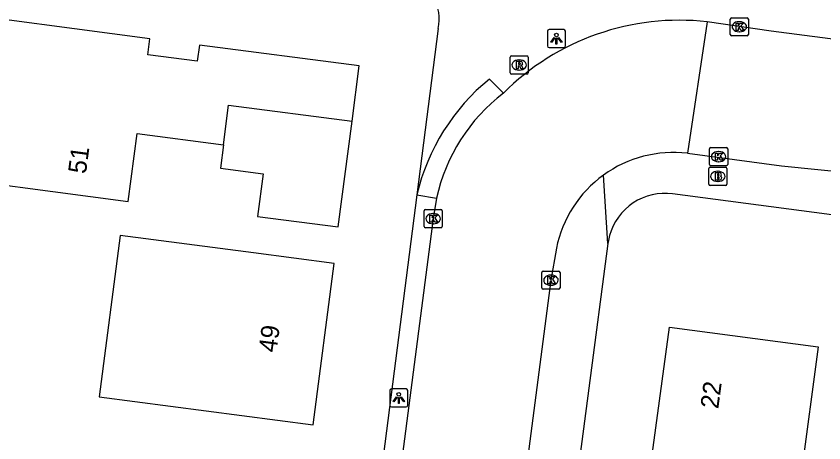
# Model space of a CAD drawing. Extents: x 162186 to 163152, y 385513 to 386513.
# Drawn here: x 162356.56 to 162401.21, y 386304.37 to 386327.96 of the extents above; entities that cross this region are included whole.
import ezdxf

# ---------------------------------------------------------------- set-up
doc = ezdxf.new("R2010")
doc.units = 0
for name, color, linetype in [('IMGEO_Brandkraan', 7, 'Continuous'), ('IMGEO_Kolk', 7, 'Continuous'), ('IMGEO_Lichtpunt', 7, 'Continuous'), ('IMGEO_Pand', 7, 'Continuous'), ('IMGEO_Pand_nummerreeks', 7, 'Continuous'), ('IMGEO_Rijbaan_lokaal_open', 7, 'Continuous'), ('IMGEO_Rioolput', 7, 'Continuous'), ('IMGEO_Voetpad_open', 7, 'Continuous')]:
    doc.layers.add(name, color=color, linetype=linetype)

msp = doc.modelspace()

# ---------------------------------------------------------------- linework, layer by layer
at = {"layer": 'IMGEO_Brandkraan'}
for p, q in [((162394.851, 386318.679), (162394.851, 386319.531)), ((162394.926, 386319.605), (162395.778, 386319.605)), ((162395.852, 386319.531), (162395.852, 386318.679)), ((162395.339, 386319.385), (162395.364, 386319.385)), ((162395.778, 386318.605), (162394.926, 386318.605)), ((162395.362, 386318.825), (162395.337, 386318.825))]:
    msp.add_line(p, q, dxfattribs=at)
for points in [[(162394.851, 386318.679), (162394.851, 386319.531)], [(162394.926, 386319.605), (162395.778, 386319.605)], [(162395.852, 386319.531), (162395.852, 386318.679)], [(162395.199, 386319.305), (162395.199, 386318.905), (162395.412, 386318.905)], [(162395.43, 386319.305), (162395.199, 386319.305)], [(162395.378, 386319.224), (162395.324, 386319.224), (162395.324, 386319.148)], [(162395.324, 386319.148), (162395.377, 386319.148)], [(162395.386, 386319.072), (162395.324, 386319.072), (162395.324, 386318.991)], [(162395.324, 386318.991), (162395.386, 386318.991)], [(162395.778, 386318.605), (162394.926, 386318.605)]]:
    msp.add_lwpolyline(points, dxfattribs=at)
for centre, radius, start, end in [((162394.928, 386319.529), 0.0765, 91.552, 178.448), ((162394.928, 386319.529), 0.0765, 91.552, 178.448), ((162395.776, 386319.529), 0.0765, 1.552, 88.448), ((162395.776, 386319.529), 0.0765, 1.552, 88.448), ((162395.379, 386319.186), 0.0379, 267.8285, 90.9355), ((162395.387, 386319.031), 0.0404, 269.8759, 90.5077), ((162395.434, 386319.16), 0.145, 59.4692, 91.5367), ((162395.459, 386319.207), 0.0922, 285.5137, 58.1501), ((162395.464, 386319.015), 0.105, 301.3115, 78.989), ((162394.928, 386318.681), 0.0765, 181.552, 268.448), ((162394.928, 386318.681), 0.0765, 181.552, 268.448), ((162395.418, 386319.156), 0.251, 268.6676, 293.5347), ((162395.776, 386318.681), 0.0765, 271.552, 358.448), ((162395.776, 386318.681), 0.0765, 271.552, 358.448)]:
    msp.add_arc(centre, radius, start, end, dxfattribs=at)
for centre, major_axis, ratio, start_param, end_param in [((162395.338, 386319.105), (-0.387, 0.002), 0.722429, 4.712389, 7.853982), ((162395.363, 386319.105), (-0.39, 0.002), 0.717154, 1.570796, 4.712389)]:
    msp.add_ellipse(centre, major_axis=major_axis, ratio=ratio, start_param=start_param, end_param=end_param, dxfattribs=at)
at = {"layer": 'IMGEO_Kolk'}
for p, q in [((162396.037, 386326.951), (162396.037, 386327.803)), ((162396.112, 386327.877), (162396.964, 386327.877)), ((162396.525, 386327.657), (162396.55, 386327.657)), ((162397.038, 386327.803), (162397.038, 386326.951)), ((162396.548, 386327.097), (162396.523, 386327.097)), ((162396.964, 386326.877), (162396.112, 386326.877)), ((162394.892, 386319.77), (162394.892, 386320.622)), ((162394.967, 386320.696), (162395.819, 386320.696)), ((162395.38, 386320.476), (162395.405, 386320.476)), ((162395.893, 386320.622), (162395.893, 386319.77)), ((162395.403, 386319.916), (162395.378, 386319.916)), ((162395.819, 386319.696), (162394.967, 386319.696)), ((162379.111, 386316.342), (162379.111, 386317.194)), ((162379.186, 386317.268), (162380.038, 386317.268)), ((162380.112, 386317.194), (162380.112, 386316.342)), ((162379.599, 386317.048), (162379.624, 386317.048)), ((162379.622, 386316.488), (162379.597, 386316.488)), ((162380.038, 386316.268), (162379.186, 386316.268)), ((162385.624, 386312.94), (162385.624, 386313.792)), ((162385.699, 386313.866), (162386.551, 386313.866)), ((162386.112, 386313.646), (162386.137, 386313.646)), ((162386.625, 386313.792), (162386.625, 386312.94)), ((162386.551, 386312.866), (162385.699, 386312.866)), ((162386.135, 386313.086), (162386.11, 386313.086))]:
    msp.add_line(p, q, dxfattribs=at)
for points in [[(162396.037, 386326.951), (162396.037, 386327.803)], [(162396.112, 386327.877), (162396.964, 386327.877)], [(162396.358, 386327.577), (162396.481, 386327.577), (162396.481, 386327.426), (162396.611, 386327.577), (162396.775, 386327.577), (162396.629, 386327.426), (162396.782, 386327.177), (162396.63, 386327.177), (162396.545, 386327.341), (162396.481, 386327.274), (162396.481, 386327.177), (162396.358, 386327.177), (162396.358, 386327.577)], [(162397.038, 386327.803), (162397.038, 386326.951)], [(162396.964, 386326.877), (162396.112, 386326.877)], [(162394.892, 386319.77), (162394.892, 386320.622)], [(162394.967, 386320.696), (162395.819, 386320.696)], [(162395.213, 386320.396), (162395.336, 386320.396), (162395.336, 386320.245), (162395.466, 386320.396), (162395.63, 386320.396), (162395.484, 386320.245), (162395.637, 386319.996), (162395.485, 386319.996), (162395.4, 386320.16), (162395.336, 386320.093), (162395.336, 386319.996), (162395.213, 386319.996), (162395.213, 386320.396)], [(162395.893, 386320.622), (162395.893, 386319.77)], [(162395.819, 386319.696), (162394.967, 386319.696)], [(162379.111, 386316.342), (162379.111, 386317.194)], [(162379.186, 386317.268), (162380.038, 386317.268)], [(162380.112, 386317.194), (162380.112, 386316.342)], [(162379.432, 386316.968), (162379.555, 386316.968), (162379.555, 386316.817), (162379.685, 386316.968), (162379.849, 386316.968), (162379.703, 386316.817), (162379.856, 386316.568), (162379.704, 386316.568), (162379.619, 386316.732), (162379.555, 386316.665), (162379.555, 386316.568), (162379.432, 386316.568), (162379.432, 386316.968)], [(162380.038, 386316.268), (162379.186, 386316.268)], [(162385.624, 386312.94), (162385.624, 386313.792)], [(162385.699, 386313.866), (162386.551, 386313.866)], [(162386.625, 386313.792), (162386.625, 386312.94)], [(162385.945, 386313.566), (162386.068, 386313.566), (162386.068, 386313.415), (162386.198, 386313.566), (162386.362, 386313.566), (162386.216, 386313.415), (162386.369, 386313.166), (162386.217, 386313.166), (162386.132, 386313.33), (162386.068, 386313.263), (162386.068, 386313.166), (162385.945, 386313.166), (162385.945, 386313.566)], [(162386.551, 386312.866), (162385.699, 386312.866)]]:
    msp.add_lwpolyline(points, dxfattribs=at)
for centre, start, end in [((162396.114, 386327.801), 91.552, 178.448), ((162396.114, 386327.801), 91.552, 178.448), ((162396.962, 386327.801), 1.552, 88.448), ((162396.962, 386327.801), 1.552, 88.448), ((162396.114, 386326.953), 181.552, 268.448), ((162396.114, 386326.953), 181.552, 268.448), ((162396.962, 386326.953), 271.552, 358.448), ((162396.962, 386326.953), 271.552, 358.448), ((162394.969, 386320.62), 91.552, 178.448), ((162394.969, 386320.62), 91.552, 178.448), ((162395.817, 386320.62), 1.552, 88.448), ((162395.817, 386320.62), 1.552, 88.448), ((162394.969, 386319.772), 181.552, 268.448), ((162394.969, 386319.772), 181.552, 268.448), ((162395.817, 386319.772), 271.552, 358.448), ((162395.817, 386319.772), 271.552, 358.448), ((162379.188, 386317.192), 91.552, 178.448), ((162379.188, 386317.192), 91.552, 178.448), ((162380.036, 386317.192), 1.552, 88.448), ((162380.036, 386317.192), 1.552, 88.448), ((162379.188, 386316.344), 181.552, 268.448), ((162379.188, 386316.344), 181.552, 268.448), ((162380.036, 386316.344), 271.552, 358.448), ((162380.036, 386316.344), 271.552, 358.448), ((162385.701, 386313.79), 91.552, 178.448), ((162385.701, 386313.79), 91.552, 178.448), ((162386.549, 386313.79), 1.552, 88.448), ((162386.549, 386313.79), 1.552, 88.448), ((162385.701, 386312.942), 181.552, 268.448), ((162385.701, 386312.942), 181.552, 268.448), ((162386.549, 386312.942), 271.552, 358.448), ((162386.549, 386312.942), 271.552, 358.448)]:
    msp.add_arc(centre, 0.0765, start, end, dxfattribs=at)
for centre, major_axis, ratio, start_param, end_param in [((162396.524, 386327.377), (-0.387, 0.002), 0.722429, 4.712389, 7.853982), ((162396.549, 386327.377), (-0.39, 0.002), 0.717154, 1.570796, 4.712389), ((162395.379, 386320.196), (-0.387, 0.002), 0.722429, 4.712389, 7.853982), ((162395.404, 386320.196), (-0.39, 0.002), 0.717154, 1.570796, 4.712389), ((162379.598, 386316.768), (-0.387, 0.002), 0.722429, 4.712389, 7.853982), ((162379.623, 386316.768), (-0.39, 0.002), 0.717154, 1.570796, 4.712389), ((162386.111, 386313.366), (-0.387, 0.002), 0.722429, 4.712389, 7.853982), ((162386.136, 386313.366), (-0.39, 0.002), 0.717154, 1.570796, 4.712389)]:
    msp.add_ellipse(centre, major_axis=major_axis, ratio=ratio, start_param=start_param, end_param=end_param, dxfattribs=at)
at = {"layer": 'IMGEO_Lichtpunt'}
for p, q in [((162385.926, 386327.124), (162385.926, 386326.317)), ((162385.926, 386327.124), (162385.926, 386326.317)), ((162386.828, 386327.219), (162386.02, 386327.219)), ((162386.828, 386327.219), (162386.02, 386327.219)), ((162386.922, 386326.317), (162386.922, 386327.124)), ((162386.922, 386326.317), (162386.922, 386327.124)), ((162386.02, 386326.223), (162386.828, 386326.223)), ((162386.02, 386326.223), (162386.828, 386326.223)), ((162377.212, 386307.261), (162377.212, 386306.454)), ((162377.212, 386307.261), (162377.212, 386306.454)), ((162378.114, 386307.356), (162377.306, 386307.356)), ((162378.114, 386307.356), (162377.306, 386307.356)), ((162378.208, 386306.454), (162378.208, 386307.261)), ((162378.208, 386306.454), (162378.208, 386307.261)), ((162377.306, 386306.36), (162378.114, 386306.36)), ((162377.306, 386306.36), (162378.114, 386306.36))]:
    msp.add_line(p, q, dxfattribs=at)
for points in [[(162386.3, 386326.788), (162386.339, 386326.76), (162386.151, 386326.498), (162386.113, 386326.525), (162386.3, 386326.788)], [(162386.402, 386326.74), (162386.449, 386326.74), (162386.449, 386326.418), (162386.402, 386326.418), (162386.402, 386326.74)], [(162386.512, 386326.76), (162386.55, 386326.787), (162386.737, 386326.525), (162386.698, 386326.497), (162386.512, 386326.76)], [(162377.586, 386306.925), (162377.625, 386306.897), (162377.437, 386306.635), (162377.399, 386306.662), (162377.586, 386306.925)], [(162377.798, 386306.897), (162377.836, 386306.924), (162378.023, 386306.662), (162377.984, 386306.634), (162377.798, 386306.897)], [(162377.688, 386306.877), (162377.735, 386306.877), (162377.735, 386306.555), (162377.688, 386306.555), (162377.688, 386306.877)]]:
    msp.add_lwpolyline(points, dxfattribs=at)
for centre in [(162386.425, 386326.922), (162377.711, 386307.059)]:
    msp.add_circle(centre, 0.0994, dxfattribs=at)
for centre, start, end in [((162386.02, 386327.124), 90, 180), ((162386.02, 386327.124), 90, 180), ((162386.828, 386327.124), 0, 90), ((162386.828, 386327.124), 0, 90), ((162386.02, 386326.317), 180, 270), ((162386.02, 386326.317), 180, 270), ((162386.828, 386326.317), 270, 0), ((162386.828, 386326.317), 270, 360), ((162377.306, 386307.261), 90, 180), ((162377.306, 386307.261), 90, 180), ((162378.114, 386307.261), 0, 90), ((162378.114, 386307.261), 0, 90), ((162377.306, 386306.454), 180, 270), ((162377.306, 386306.454), 180, 270), ((162378.114, 386306.454), 270, 0), ((162378.114, 386306.454), 270, 360)]:
    msp.add_arc(centre, 0.0946, start, end, dxfattribs=at)
at = {"layer": 'IMGEO_Pand'}
for points in [[(162375.128, 386322.164), (162375.526, 386325.207), (162366.69, 386326.363), (162366.573, 386325.47), (162363.832, 386325.817), (162363.95, 386326.709), (162351.713, 386328.332)], [(162368.022, 386320.846), (162368.303, 386323.043), (162375.128, 386322.164)], [(162368.022, 386320.846), (162367.854, 386319.563), (162370.212, 386319.254), (162369.903, 386316.893), (162374.363, 386316.31), (162375.128, 386322.164)], [(162350.519, 386319.333), (162362.755, 386317.709), (162363.254, 386321.469), (162368.022, 386320.846)], [(162362.317, 386315.834), (162361.15, 386306.922), (162372.969, 386305.375), (162374.136, 386314.287), (162369.676, 386314.871), (162362.317, 386315.834)], [(162391.728, 386303.721), (162392.669, 386310.772), (162400.894, 386309.674), (162399.957, 386302.646)]]:
    msp.add_lwpolyline(points, dxfattribs=at)
at = {"layer": 'IMGEO_Rijbaan_lokaal_open'}
for points in [[(162394.765, 386327.647), (162393.671, 386320.383)], [(162424.113, 386323.778), (162398.306, 386327.127), (162394.765, 386327.647)], [(162393.671, 386320.383), (162398.862, 386319.696), (162408.726, 386318.7)], [(162379.793, 386317.9), (162379.612, 386316.768), (162376.278, 386291.138)], [(162386.424, 386315.134), (162386.125, 386313.366), (162383.65, 386294.444), (162380.866, 386272.311)]]:
    msp.add_lwpolyline(points, dxfattribs=at)
for centre, radius, start, end in [((162393.217, 386313.993), 13.742, 83.5336, 135.0447), ((162389.59, 386315.733), 10.034, 127.4199, 167.5279), ((162392.902, 386313.821), 6.607, 83.3131, 125.9287), ((162392.903, 386313.816), 6.612, 125.9111, 168.5024)]:
    msp.add_arc(centre, radius, start, end, dxfattribs=at)
at = {"layer": 'IMGEO_Rioolput'}
for p, q in [((162383.864, 386324.835), (162383.864, 386325.687)), ((162383.939, 386325.761), (162384.791, 386325.761)), ((162384.865, 386325.687), (162384.865, 386324.835)), ((162384.352, 386325.541), (162384.377, 386325.541)), ((162384.375, 386324.981), (162384.35, 386324.981)), ((162384.791, 386324.761), (162383.939, 386324.761))]:
    msp.add_line(p, q, dxfattribs=at)
for points in [[(162383.864, 386324.835), (162383.864, 386325.687)], [(162383.939, 386325.761), (162384.791, 386325.761)], [(162384.865, 386325.687), (162384.865, 386324.835)], [(162384.453, 386325.459), (162384.201, 386325.461), (162384.201, 386325.061)], [(162384.379, 386325.38), (162384.325, 386325.38), (162384.325, 386325.299)], [(162384.325, 386325.299), (162384.377, 386325.299)], [(162384.201, 386325.061), (162384.325, 386325.061), (162384.325, 386325.223), (162384.336, 386325.223)], [(162384.383, 386325.194), (162384.454, 386325.061), (162384.594, 386325.061), (162384.529, 386325.187)], [(162384.791, 386324.761), (162383.939, 386324.761)]]:
    msp.add_lwpolyline(points, dxfattribs=at)
for centre, radius, start, end in [((162383.941, 386325.685), 0.0765, 91.552, 178.448), ((162383.941, 386325.685), 0.0765, 91.552, 178.448), ((162384.789, 386325.685), 0.0765, 1.552, 88.448), ((162384.789, 386325.685), 0.0765, 1.552, 88.448), ((162384.361, 386325.488), 0.19, 274.7715, 282.9687), ((162384.385, 386325.284), 0.0964, 77.0061, 93.1865), ((162384.399, 386325.341), 0.0378, 276.6634, 79.6772), ((162384.452, 386325.349), 0.109, 350.3612, 89.416), ((162384.45, 386325.349), 0.112, 277.5842, 350.9817), ((162384.434, 386325.134), 0.108, 29.5134, 73.7905), ((162383.941, 386324.837), 0.0765, 181.552, 268.448), ((162383.941, 386324.837), 0.0765, 181.552, 268.448), ((162384.335, 386325.17), 0.0533, 26.0293, 88.6989), ((162384.789, 386324.837), 0.0765, 271.552, 358.448), ((162384.789, 386324.837), 0.0765, 271.552, 358.448)]:
    msp.add_arc(centre, radius, start, end, dxfattribs=at)
for centre, major_axis, ratio, start_param, end_param in [((162384.351, 386325.261), (-0.387, 0.002), 0.722429, 4.712389, 7.853982), ((162384.376, 386325.261), (-0.39, 0.002), 0.717154, 1.570796, 4.712389)]:
    msp.add_ellipse(centre, major_axis=major_axis, ratio=ratio, start_param=start_param, end_param=end_param, dxfattribs=at)
at = {"layer": 'IMGEO_Voetpad_open'}
for points in [[(162379.888, 386327.273), (162378.714, 386318.092)], [(162382.72, 386324.485), (162383.493, 386323.702)], [(162389.272, 386315.389), (162389.025, 386319.171)], [(162378.714, 386318.092), (162375.27, 386291.27)], [(162378.714, 386318.092), (162379.793, 386317.9)], [(162411.863, 386315.638), (162392.843, 386318.138), (162392.559, 386318.162), (162392.275, 386318.161), (162391.991, 386318.135), (162391.711, 386318.083), (162391.437, 386318.007), (162391.171, 386317.906), (162390.915, 386317.782), (162390.671, 386317.635), (162390.441, 386317.468), (162390.227, 386317.28), (162390.03, 386317.074), (162389.853, 386316.852), (162389.696, 386316.614), (162389.561, 386316.363), (162389.449, 386316.102), (162389.361, 386315.831), (162389.298, 386315.554), (162389.272, 386315.389)], [(162389.272, 386315.389), (162385.064, 386283.402), (162384.389, 386283.49), (162383.167, 386273.781)]]:
    msp.add_lwpolyline(points, dxfattribs=at)
for centre, radius, start, end in [((162377.603, 386327.803), 2.346, 346.9452, 73.1741), ((162390.167, 386315.367), 11.773, 129.2403, 166.6153)]:
    msp.add_arc(centre, radius, start, end, dxfattribs=at)

# ---------------------------------------------------------------- texts
at = {"layer": 'IMGEO_Pand_nummerreeks'}
for s, rotation, p in [('51', 82.4403, (162360.413, 386319.214)), ('49', 82.5397, (162370.946, 386309.339)), ('22', 82.4019, (162395.371, 386306.223))]:
    msp.add_text(s, height=1, rotation=rotation, dxfattribs=at).set_placement(p)

doc.saveas('drawing.dxf')
